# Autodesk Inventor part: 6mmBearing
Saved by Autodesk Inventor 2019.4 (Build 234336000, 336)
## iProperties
Created: 2020-04
Part Number: 6mmBearing
Material: Generic
Document SubType Name: Modeling
Designer: Administrator
Density: 1 g/cm^3
Appearance: Default
Title: 6mmBearing v2
Author: Administrator
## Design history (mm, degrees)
feature "Body1"
body "Solid1"
